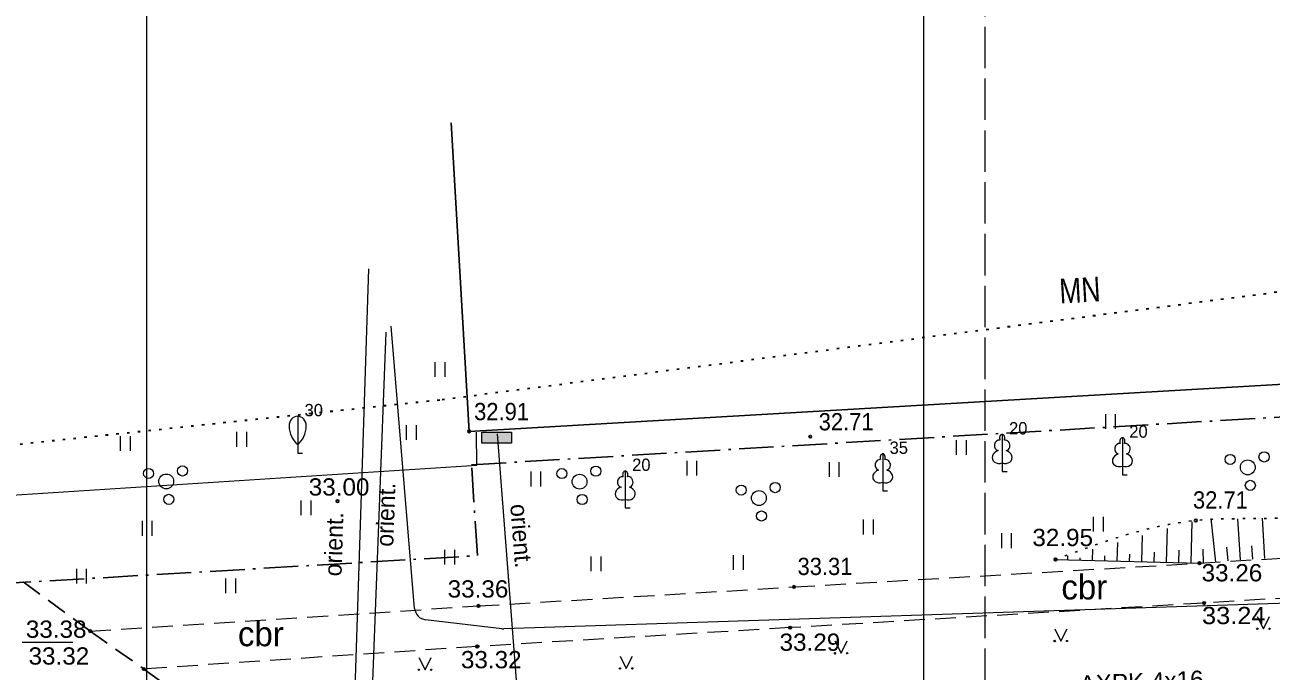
# Model space of a CAD drawing. Extents: x 380758 to 381729, y 283236 to 283533.
# Drawn here: x 381313.6 to 381364.1, y 283359.1 to 283385.3 of the extents above; entities that cross this region are included whole.
import ezdxf
from ezdxf.enums import TextEntityAlignment as Align

# ---------------------------------------------------------------- set-up
doc = ezdxf.new("R2010")
doc.units = 0
doc.header["$LTSCALE"] = 0.28
for name, pattern in [('DOT_DASHED', [7.7, 5, -1.2, 0.3, -1.2]), ('DOTTED', [1.5, 0.3, -1.2]), ('LONG_DASHED', [7.5, 6, -1.5]), ('MEDIUM_DASHED', [4.5, 3, -1.5])]:
    doc.linetypes.add(name, pattern=pattern)
for name, color, linetype, lineweight in [('1', 7, 'Continuous', 13), ('18', 7, 'Continuous', 13), ('23', 7, 'Continuous', 13), ('25', 7, 'DOTTED', 35), ('29', 7, 'DOT_DASHED', 25), ('31', 7, 'Continuous', 13), ('35', 7, 'Continuous', 13), ('37', 7, 'MEDIUM_DASHED', 13), ('4', 7, 'Continuous', 13), ('40', 7, 'Continuous', 25), ('45', 7, 'Continuous', 13), ('47', 7, 'Continuous', 13), ('58', 7, 'Continuous', 25), ('63', 7, 'Continuous', 13), ('7', 7, 'Continuous', 13), ('9', 7, 'Continuous', 13)]:
    doc.layers.add(name, color=color, linetype=linetype, lineweight=lineweight)

msp = doc.modelspace()

# ---------------------------------------------------------------- hatches: boundary and pattern name
at = {"layer": '18'}
msp.add_hatch(color=256, dxfattribs=at).paths.add_polyline_path([(381332.074, 283368.794), (381333.274, 283368.794), (381333.274, 283368.344), (381332.074, 283368.344)])

# ---------------------------------------------------------------- linework, layer by layer
at = {"layer": '1'}
for p, q in [((381324.612, 283369.434), (381324.612, 283368.286)), ((381353.166, 283368.698), (381353.166, 283367.545)), ((381358.039, 283368.565), (381358.039, 283367.412)), ((381324.612, 283368.286), (381324.612, 283367.934)), ((381353.256, 283368.466), (381353.255, 283368.467)), ((381358.129, 283368.333), (381358.128, 283368.334)), ((381324.612, 283367.934), (381324.812, 283367.934)), ((381348.324, 283367.911), (381348.324, 283366.758)), ((381348.414, 283367.679), (381348.413, 283367.68)), ((381353.166, 283367.545), (381353.166, 283367.198)), ((381337.889, 283367.218), (381337.889, 283366.065)), ((381337.979, 283366.986), (381337.978, 283366.987)), ((381353.166, 283367.198), (381353.366, 283367.198)), ((381358.039, 283367.412), (381358.039, 283367.065)), ((381358.039, 283367.065), (381358.239, 283367.065)), ((381348.324, 283366.758), (381348.324, 283366.411)), ((381337.889, 283366.065), (381337.889, 283365.718)), ((381348.324, 283366.411), (381348.524, 283366.411)), ((381337.889, 283365.718), (381338.089, 283365.718))]:
    msp.add_line(p, q, dxfattribs=at)
for centre, radius in [((381363.7824, 283367.7862), 0.2066), ((381362.4068, 283367.6852), 0.2041), ((381363.1209, 283367.3613), 0.3006), ((381318.5678, 283367.1172), 0.2041), ((381319.2819, 283366.7933), 0.3006), ((381319.9434, 283367.2182), 0.2066), ((381335.3228, 283367.1092), 0.2041), ((381336.0369, 283366.7853), 0.3006), ((381336.6984, 283367.2102), 0.2066), ((381342.5918, 283366.4422), 0.2041), ((381343.9674, 283366.5432), 0.2066), ((381363.2242, 283366.6338), 0.2045), ((381319.3852, 283366.0658), 0.2045), ((381336.1402, 283366.0578), 0.2045), ((381343.3059, 283366.1183), 0.3006), ((381343.4092, 283365.3908), 0.2045)]:
    msp.add_circle(centre, radius, dxfattribs=at)
for centre, major_axis, ratio, start_param, end_param in [((381324.612, 283369.034), (0, 0.4), 0.875, 0, 1.5707963), ((381325.0873, 283369.0574), (0, -0.9434), 0.875, 4.7372004, 5.6697113), ((381324.612, 283369.034), (0, -0.4), 0.875, 1.5707963, 3.1415927), ((381324.612, 283369.034), (0, -0.4), 0.875, 1.5707963, 3.1415927), ((381324.1367, 283369.0574), (0, -0.9434), 0.875, 0.613474, 1.5459849), ((381353.1664, 283368.5481), (0, -0.1499), 0.707107, 3.1453698, 5.2874846), ((381353.1656, 283368.5481), (0, -0.1499), 0.707107, 0.9957007, 3.1378155), ((381358.0394, 283368.4151), (0, -0.1499), 0.707107, 3.1453698, 5.2874846), ((381358.0386, 283368.4151), (0, -0.1499), 0.707107, 0.9957007, 3.1378155), ((381353.0764, 283367.7909), (0.3068, 0.0951), 0.814445, 1.5707963, 4.7520146), ((381353.0377, 283368.2532), (-0.0387, -0.2124), 0.861323, 3.1415927, 6.2831853), ((381353.2556, 283367.7909), (-0.3068, 0.0951), 0.814445, 1.5311707, 4.712389), ((381353.2943, 283368.2532), (0.0387, -0.2124), 0.861323, 6.2831853, 9.424778), ((381357.9107, 283368.1202), (-0.0387, -0.2124), 0.861323, 3.1415927, 6.2831853), ((381358.1673, 283368.1202), (0.0387, -0.2124), 0.861323, 6.2831853, 9.424778), ((381348.1957, 283367.4662), (-0.0387, -0.2124), 0.861323, 3.1415927, 6.2831853), ((381348.3244, 283367.7611), (0, -0.1499), 0.707107, 3.1453698, 5.2874846), ((381348.3236, 283367.7611), (0, -0.1499), 0.707107, 0.9957007, 3.1378155), ((381348.4523, 283367.4662), (0.0387, -0.2124), 0.861323, 6.2831853, 9.424778), ((381357.9494, 283367.6579), (0.3068, 0.0951), 0.814445, 1.5707963, 4.7520146), ((381358.1286, 283367.6579), (-0.3068, 0.0951), 0.814445, 1.5311707, 4.712389), ((381337.7607, 283366.7732), (-0.0387, -0.2124), 0.861323, 3.1415927, 6.2831853), ((381337.8894, 283367.0681), (0, -0.1499), 0.707107, 3.1453698, 5.2874846), ((381337.8886, 283367.0681), (0, -0.1499), 0.707107, 0.9957007, 3.1378155), ((381338.0173, 283366.7732), (0.0387, -0.2124), 0.861323, 6.2831853, 9.424778), ((381348.2344, 283367.0039), (0.3068, 0.0951), 0.814445, 1.5707963, 4.7520146), ((381348.4136, 283367.0039), (-0.3068, 0.0951), 0.814445, 1.5311707, 4.712389), ((381337.7994, 283366.3109), (0.3068, 0.0951), 0.814445, 1.5707963, 4.7520146), ((381337.9786, 283366.3109), (-0.3068, 0.0951), 0.814445, 1.5311707, 4.712389)]:
    msp.add_ellipse(centre, major_axis=major_axis, ratio=ratio, start_param=start_param, end_param=end_param, dxfattribs=at)
at = {"layer": '18'}
msp.add_lwpolyline([(381332.074, 283368.794), (381333.274, 283368.794), (381333.274, 283368.344), (381332.074, 283368.344)], close=True, dxfattribs=at)
at = {"layer": '23'}
for p, q in [((381330.187, 283371.031), (381330.187, 283371.631)), ((381330.587, 283371.031), (381330.587, 283371.631)), ((381357.366, 283368.922), (381357.366, 283369.522)), ((381357.766, 283368.922), (381357.766, 283369.522)), ((381329.023, 283368.477), (381329.023, 283369.077)), ((381329.423, 283368.477), (381329.423, 283369.077)), ((381317.43, 283368.033), (381317.43, 283368.633)), ((381317.83, 283368.033), (381317.83, 283368.633)), ((381322.145, 283368.2), (381322.145, 283368.8)), ((381322.545, 283368.2), (381322.545, 283368.8)), ((381351.32, 283367.867), (381351.32, 283368.467)), ((381351.72, 283367.867), (381351.72, 283368.467)), ((381340.393, 283367.034), (381340.393, 283367.634)), ((381340.793, 283367.034), (381340.793, 283367.634)), ((381346.162, 283366.979), (381346.162, 283367.579)), ((381346.562, 283366.979), (381346.562, 283367.579)), ((381334.07, 283366.59), (381334.07, 283367.19)), ((381334.47, 283366.59), (381334.47, 283367.19)), ((381324.752, 283365.425), (381324.752, 283366.025)), ((381325.152, 283365.425), (381325.152, 283366.025)), ((381318.318, 283364.592), (381318.318, 283365.192)), ((381318.718, 283364.592), (381318.718, 283365.192)), ((381347.548, 283364.648), (381347.548, 283365.248)), ((381347.948, 283364.648), (381347.948, 283365.248)), ((381356.867, 283364.759), (381356.867, 283365.359)), ((381357.267, 283364.759), (381357.267, 283365.359)), ((381353.15, 283364.093), (381353.15, 283364.693)), ((381353.55, 283364.093), (381353.55, 283364.693)), ((381330.576, 283363.426), (381330.576, 283364.026)), ((381330.976, 283363.426), (381330.976, 283364.026)), ((381336.511, 283363.149), (381336.511, 283363.749)), ((381336.911, 283363.149), (381336.911, 283363.749)), ((381342.279, 283363.204), (381342.279, 283363.804)), ((381342.679, 283363.204), (381342.679, 283363.804)), ((381315.655, 283362.649), (381315.655, 283363.249)), ((381316.055, 283362.649), (381316.055, 283363.249)), ((381321.701, 283362.261), (381321.701, 283362.861)), ((381322.101, 283362.261), (381322.101, 283362.861))]:
    msp.add_line(p, q, dxfattribs=at)
for points in [[(381363.503, 283361.323), (381363.753, 283360.823), (381364.003, 283361.323)], [(381355.294, 283360.824), (381355.544, 283360.324), (381355.794, 283360.824)], [(381346.384, 283360.325), (381346.634, 283359.825), (381346.884, 283360.325)], [(381329.523, 283359.659), (381329.773, 283359.159), (381330.023, 283359.659)], [(381337.676, 283359.715), (381337.926, 283359.215), (381338.176, 283359.715)]]:
    msp.add_lwpolyline(points, dxfattribs=at)
for centre, radius in [((381363.5029, 283360.823), 0.028), ((381364.0029, 283360.823), 0.0263), ((381355.2939, 283360.3235), 0.028), ((381355.7939, 283360.3235), 0.0263), ((381346.384, 283359.825), 0.028), ((381346.884, 283359.825), 0.0263), ((381329.5224, 283359.1589), 0.028), ((381330.0224, 283359.1589), 0.0263), ((381337.6759, 283359.2144), 0.028), ((381338.1759, 283359.2144), 0.0263)]:
    msp.add_circle(centre, radius, dxfattribs=at)
at = {"layer": '25'}
msp.add_lwpolyline([(381378.132, 283376.241), (381330.368, 283370.09), (381282.589, 283365.052), (381241.341, 283362.776), (381227.597, 283363.335), (381201.225, 283361.612), (381131.764, 283357.382), (381089.163, 283355.29), (381056.824, 283352.96), (381046.619, 283367.047), (381043.733, 283420.739)], dxfattribs=at)
at = {"layer": '29'}
msp.add_lwpolyline([(381295.048, 283361.612), (381331.894, 283363.785), (381331.661, 283367.471), (381474.583, 283375.901), (381472.771, 283396.509)], dxfattribs=at)
at = {"layer": '31'}
for p, q in [((381360.827, 283363.49), (381360.87, 283365.16)), ((381361.826, 283363.517), (381361.634, 283365.293)), ((381362.821, 283363.609), (381362.722, 283365.275)), ((381363.819, 283363.668), (381363.723, 283365.301)), ((381358.828, 283363.541), (381358.855, 283364.6)), ((381359.827, 283363.515), (381359.863, 283364.88)), ((381356.828, 283363.592), (381356.84, 283364.041)), ((381357.828, 283363.567), (381357.848, 283364.321)), ((381360.327, 283363.503), (381360.34, 283364.002)), ((381361.327, 283363.481), (381361.314, 283364.05)), ((381362.322, 283363.573), (381362.266, 283364.127)), ((381363.32, 283363.639), (381363.288, 283364.183)), ((381355.329, 283363.631), (381361.164, 283363.481)), ((381355.829, 283363.618), (381355.833, 283363.771)), ((381356.329, 283363.605), (381356.331, 283363.697)), ((381357.328, 283363.58), (381357.333, 283363.773)), ((381358.328, 283363.554), (381358.336, 283363.849)), ((381359.328, 283363.528), (381359.338, 283363.926))]:
    msp.add_line(p, q, dxfattribs=at)
at = {"layer": '31', "linetype": 'DOTTED', "lineweight": 25}
msp.add_spline([(381450.06, 283369.523), (381434.895, 283369.681), (381416.392, 283368.663), (381398.465, 283367.309), (381381.491, 283365.918), (381363.027, 283365.287), (381361.014, 283365.21), (381355.329, 283363.631)], degree=3, dxfattribs=at)
at = {"layer": '35'}
msp.add_lwpolyline([(381309.663, 283366.014), (381331.876, 283367.451), (381331.862, 283368.792)], dxfattribs=at)
at = {"layer": '37'}
for points in [[(381316.201, 283360.727), (381331.943, 283361.745), (381344.729, 283362.515), (381361.164, 283363.481), (381381.389, 283364.709), (381398.798, 283365.771), (381416.342, 283366.829), (381434.871, 283368.056), (381450.905, 283368.93), (381461.991, 283369.906)], [(381460.408, 283368.115), (381451.323, 283367.345), (381435.3, 283366.345), (381418.565, 283365.349), (381399.092, 283364.148), (381381.438, 283363.096), (381361.351, 283361.862), (381344.571, 283360.865), (381331.883, 283360.102), (381318.377, 283359.189)]]:
    msp.add_lwpolyline(points, dxfattribs=at)
at = {"layer": '37', "lineweight": 25}
msp.add_lwpolyline([(381309.426, 283365.712), (381316.201, 283360.727), (381318.377, 283359.189), (381320.24, 283357.84), (381330.826, 283355.148), (381345.75, 283356.042), (381361.347, 283356.997), (381379.416, 283358.112), (381395.576, 283359.052), (381419.83, 283360.537), (381435.717, 283361.494), (381453.632, 283362.598)], dxfattribs=at)
at = {"layer": '40'}
msp.add_line((381331.564, 283368.821), (381330.839, 283381.324), dxfattribs=at)
msp.add_lwpolyline([(381331.564, 283368.821), (381382.009, 283371.748), (381381.284, 283384.251)], dxfattribs=at)
at = {"layer": '47'}
msp.add_line((381327.333, 283349.98), (381328.196, 283372.843), dxfattribs=at)
at = {"layer": '58', "lineweight": 13}
msp.add_line((381313.44, 283360.273), (381315.496, 283360.273), dxfattribs=at)
at = {"layer": '58'}
for centre in [(381331.564, 283368.8211), (381345.388, 283368.6071), (381326.227, 283365.9941), (381361.014, 283365.2101), (381355.329, 283363.6311), (381361.164, 283363.4811), (381344.729, 283362.5151), (381331.943, 283361.7451), (381361.351, 283361.8621), (381344.571, 283360.8651), (381316.201, 283360.7271), (381331.883, 283360.1021), (381318.377, 283359.1891)]:
    msp.add_circle(centre, 0.0534, dxfattribs=at)
at = {"layer": '63', "linetype": 'LONG_DASHED'}
msp.add_line((381352.477, 283259.645), (381352.477, 283469.645), dxfattribs=at)
at = {"layer": '63'}
msp.add_line((381349.977, 283467.145), (381349.977, 283262.145), dxfattribs=at)
msp.add_lwpolyline([(381318.495, 283530.375), (381726.495, 283530.375), (381726.495, 283238.375), (381318.495, 283238.375)], close=True, dxfattribs=at)
at = {"layer": '7'}
for p, q in [((381329.353, 283361.642), (381328.405, 283373.086)), ((381388.178, 283362.628), (381332.963, 283360.818)), ((381332.888, 283360.821), (381329.793, 283361.186))]:
    msp.add_line(p, q, dxfattribs=at)
msp.add_lwpolyline([(381196.222, 283352.745), (381196.603, 283352.099), (381248.161, 283356.386), (381254.469, 283356.616), (381286.512, 283358.274), (381296.357, 283357.997), (381300.874, 283357.482), (381326.232, 283356.938), (381333.586, 283357.337), (381332.704, 283368.723)], dxfattribs=at)
for centre, start, end in [((381329.8513, 283361.683), 184.73429, 263.26448), ((381332.947, 283361.3174), 263.26448, 271.87814)]:
    msp.add_arc(centre, 0.5, start, end, dxfattribs=at)
at = {"layer": '9'}
msp.add_line((381326.31, 283339.103), (381327.501, 283375.405), dxfattribs=at)

# ---------------------------------------------------------------- texts
at = {"layer": '1'}
for s, p in [('30', (381324.892, 283369.434)), ('20', (381353.446, 283368.698)), ('20', (381358.319, 283368.565)), ('35', (381348.604, 283367.911)), ('20', (381338.169, 283367.218))]:
    msp.add_text(s, height=0.5, dxfattribs=at).set_placement(p)
at = {"layer": '37'}
for p in [(381356.4945, 283362.009), (381323.1205, 283360.112)]:
    msp.add_text('cbr', height=1, dxfattribs=at).set_placement(p, align=Align.CENTER)
at = {"layer": '4', "width": 0.8}
msp.add_text('MN', height=1, rotation=3.321, dxfattribs=at).set_placement((381355.513, 283374.002))
at = {"layer": '45', "width": 1.05}
msp.add_text('AXPK 4x16', height=0.7, rotation=2.412, dxfattribs=at).set_placement((381356.321, 283358.221))
at = {"layer": '47'}
msp.add_text('orient.', height=0.7, rotation=87.837, dxfattribs=at).set_placement((381328.5298, 283365.4363), align=Align.CENTER)
at = {"layer": '58'}
for s, width, p in [('32.91', 0.95, (381331.763, 283369.276)), ('32.71', 0.95, (381345.729, 283368.863)), ('33.00', 1.05, (381325.061, 283366.221)), ('32.71', 0.95, (381360.9, 283365.693)), ('32.95', 1.05, (381354.39, 283364.171)), ('33.31', 0.95, (381344.871, 283362.998)), ('33.26', 1.05, (381361.249, 283362.741)), ('33.36', 1.05, (381330.691, 283362.086)), ('33.24', 1.1, (381361.265, 283361.008)), ('33.38', 1.05, (381313.593, 283360.454)), ('33.29', 1.05, (381344.144, 283359.926)), ('33.32', 1.05, (381313.704, 283359.367)), ('33.32', 1.05, (381331.229, 283359.219))]:
    msp.add_text(s, height=0.7, dxfattribs=dict(at, width=width)).set_placement(p)
at = {"layer": '7'}
msp.add_text('orient.', height=0.7, rotation=274.431, dxfattribs=at).set_placement((381333.3276, 283364.557), align=Align.CENTER)
at = {"layer": '9'}
msp.add_text('orient.', height=0.7, rotation=88.121, dxfattribs=at).set_placement((381326.428, 283364.237), align=Align.CENTER)

doc.saveas('drawing.dxf')
